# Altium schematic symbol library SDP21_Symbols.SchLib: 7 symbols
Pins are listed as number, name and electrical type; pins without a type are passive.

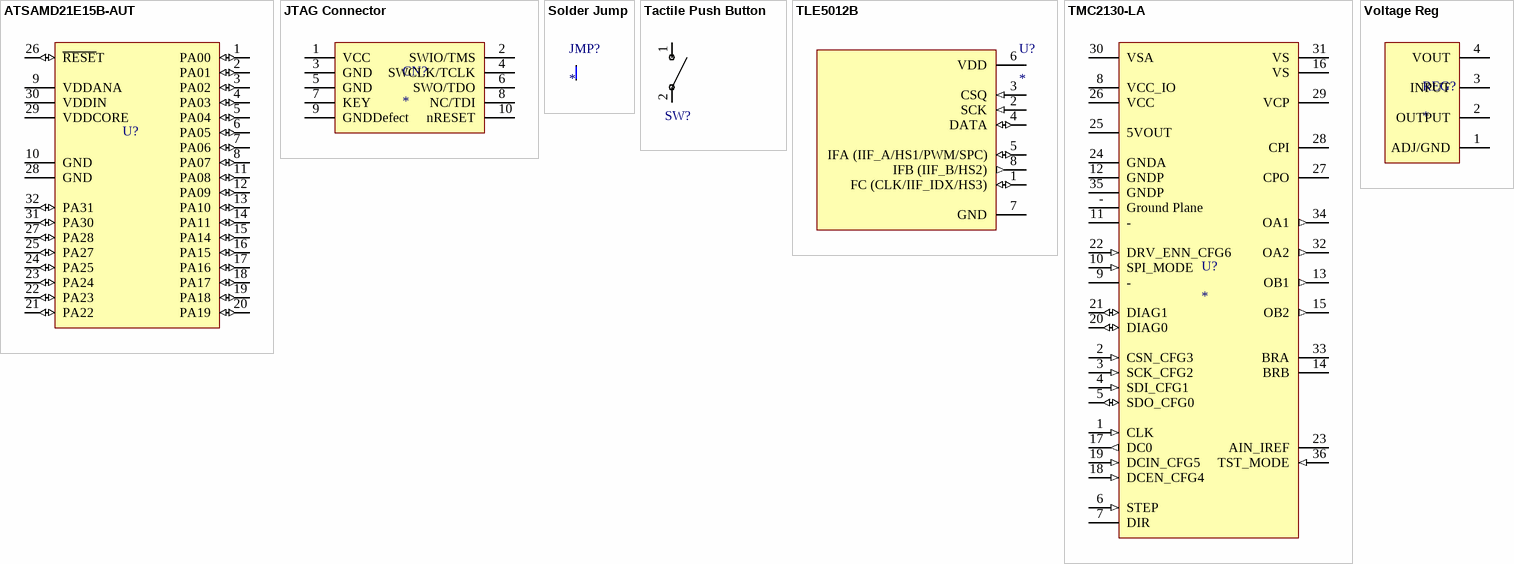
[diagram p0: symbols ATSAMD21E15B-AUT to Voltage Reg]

## ATSAMD21E15B-AUT
designator U?  (value not drawn)
IC MCU 32BIT 32KB FLASH 32TQFP
footprint TQFP-32
pins: 1 PA00 (io), 2 PA01 (io), 3 PA02 (io) "Analog", 4 PA03 (io) "Analog", 5 PA04 (io) "Analog", 6 PA05 (io) "Analog", 7 PA06 (io) "Analog", 8 PA07 (io) "Analog", 9 VDDANA (power), 10 GND (power), 11 PA08 (io) "Analog", 12 PA09 (io) "Analog", 13 PA10 (io) "Analog", 14 PA11 (io) "Analog", 15 PA14 (io), 16 PA15 (io), 17 PA16 (io), 18 PA17 (io), 19 PA18 (io), 20 PA19 (io), 21 PA22 (io), 22 PA23 (io), 23 PA24 (io), 24 PA25 (io), 25 PA27 (io), 26 ~{RESE}T (io), 27 PA28 (io), 28 GND (power), 29 VDDCORE (power), 30 VDDIN (power), 31 PA30 (io) "Analog", 32 PA31 (io) "Analog"

## JTAG Connector
designator CN?
footprint Header 5x2 - 50mil
pins: 1 VCC (power), 2 SWIO/TMS (power), 3 GND (power), 4 SWCLK/TCLK (power), 5 GND (power), 6 SWO/TDO (power), 7 KEY (power), 8 NC/TDI (power), 9 GNDDefect (power), 10 nRESET (power)

## Solder Jump
designator JMP?
footprint Solder Jump
pins: 1, 2

## Tactile Push Button
designator SW?, comment PTS525SM15SMTR2 LFS  (value not drawn)
SWITCH TACTILE SPST-NO 0.02A 15V
footprint PTS525 SM08 SMTR2 LFS
pins: 1, 2

## TLE5012B
designator U?
TLE5012B GMR-Based Angle Sensor PG-DSO-8
footprint PG-DSO-8
footprint Model Name (Footprint not found)
pins: 1 FC (CLK/IIF_IDX/HS3) (io) "Interface C: External Clock/IIF Index/Hall Switch Signal 3)", 2 SCK (in) "SSC Clock", 3 CSQ (in) "SSC Chip Select", 4 DATA (io) "SSC Data", 5 IFA (IIF_A/HS1/PWM/SPC) (io) "Interface A: IIF Phase A/Hall Switch Signal 1/PWM/SPC output (input for SPC trigger only)", 6 VDD (power) "Supply voltage", 7 GND (power) "Ground", 8 IFB (IIF_B/HS2) (out) "Interface B: IIF Phase B/Hall Switch Signal 2"

## TMC2130-LA
designator U?
TMC2130-LA Trinamic Driver QFN-36
footprint QFN-36
pins: 1 CLK (in) "CLK input. Tie to GND using short  wire for internal  clock or supply external clock.", 2 CSN_CFG3 (in) "SPI chip select input (negative active) (SPI_MODE=1) orConfiguration input (SPI_MODE=0) (tristate detection).", 3 SCK_CFG2 (in) "SPI serialclock input(SPI_MODE=1) orConfiguration input (SPI_MODE=0) (tristate detection)", 4 SDI_CFG1 (in) "SPI data input (SPI_MODE=1) or Configuration input (SPI_MODE=0) (tristate detection).", 5 SDO_CFG0 (io) "SPI data output (tristate) (SPI_MODE=1) or Configuration input (SPI_MODE=0) (tristate detection).", 6 STEP (in) "STEP input", 7 DIR, 8 VCC_IO (power) "3.3V to 5V IO supply voltage for all digital pins.", 9 - (hiz) "Do  not  connect.  Leave  opento  ensure  highest  distance for high voltage pins in TQFP package!", 10 SPI_MODE (in) "Mode selection input with pullup resistor. When tied low, the  chip  is  in  standalone  mode  and  pins  have  their  CFG functions.  When  tied  high,  the  SPI  interface  is  availablefor control. Integrated pull-up resistor.", 11 - "Unused  pin,  connect  to  GND  for  compatibility  to  future versions.", 12 GNDP (power) "Power GND. Connect to GND plane near pin.", 13 OB1 (out) "Motor coil B output 1", 14 BRB "Sense  resistor  connection  for  coil  B.  Place  sense  resistor to  GND  near  pin.  An  additional  100nF  capacitor  to  GND (GND plane) is recommended for best performance.", 15 OB2 (out) "Motor coil B output 2", 16 VS (power) "Motor  supply  voltage.  Provide  filtering  capacity  near  pin with short loop to nearest GNDP pin (respectively via GND plane).", 17 DC0 (out) "dcStep ready output", 18 DCEN_CFG4 (in) "dcStep enable input (SPI_MODE=1) -tie to GND for normal operation (no dcStep) orConfiguration input (SPI_MODE=0) (tristate detection).", 19 DCIN_CFG5 (in) "dcStep gating input for axis synchronization (SPI_MODE=1) orConfiguration input (SPI_MODE=0) (tristate detection).", 20 DIAG0 (io) "Diagnostics  output  DIAG0.  Use  external  pull-up  resistor with 47k or less in open drain mode.", 21 DIAG1 (io) "Diagnostics  output  DIAG1.  Use  external  pull-up  resistor with 47k or less in open drain mode.", 22 DRV_ENN_CFG6 (in) "Enable input (SPI_MODE=1) or configuration   /   Enable   input   (SPI_MODE=0)   (tristate detection).The power stage becomes switched off (all motor outputs floating) when this pin becomes driven to a high level.", 23 AIN_IREF "Analog  reference  voltage  for  current  scaling  (optional mode)  or  reference  current  for  use  of  internal  sense resistors", 24 GNDA (power) "Analog GND. Tie to GND plane.", 25 5VOUT (power) "Output  of  internal  5V  regulator.  Attach  2.2μF  or  larger ceramic   capacitor   to   GNDA   near   to   pin   for   best performance. May be used to supply VCC of chip.", 26 VCC (power) "5V  supply  input  for  digital  circuitry  within  chip  and chargepump. Attach 470nF capacitor to GND (GND plane). May  be  supplied  by  5VOUT.  A  2.2  or  3.3  Ohm  resistor  is recommended  for  decoupling  noise  from  5VOUT.  When using  an  external  supply,  make  sure,  that  VCC  comes  up before  or  in  parallel  to  5VOUT  or  VCC_IO,  whichever comes up later!", 27 CPO "Charge pump capacitor output.", 28 CPI "Charge pump capacitor input.Tie to CPO using 22nF  50V capacitor.", 29 VCP "Charge pump voltage.Tie to VS using 100nF capacitor.", 30 VSA (power) "Analog  supply  voltage  for  5V  regulator.  Normally  tied  to VS. Provide a 100nF filtering capacitor.", 31 VS (power) "Motor  supply  voltage.  Provide  filtering  capacity  near  pin with short loop to nearest GNDP pin (respectively via GND plane).", 32 OA2 (out) "Motor coil A output 2", 33 BRA "Sense  resistor  connection  for  coil  A.  Place  sense  resistor to  GND  near  pin.  An  additional  100nF  capacitor  to  GND (GND plane) is recommended for bestperformance.", 34 OA1 (out) "Motor coil A output 1", 35 GNDP (power) "Power GND. Connect to GND plane near pin.", 36 TST_MODE (in) "Test mode input. Tie to GND using short wire.", - Ground Plane

## Voltage Reg
designator REG?
footprint SOT223
pins: 1 ADJ/GND, 2 OUTPUT, 3 INPUT, 4 VOUT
